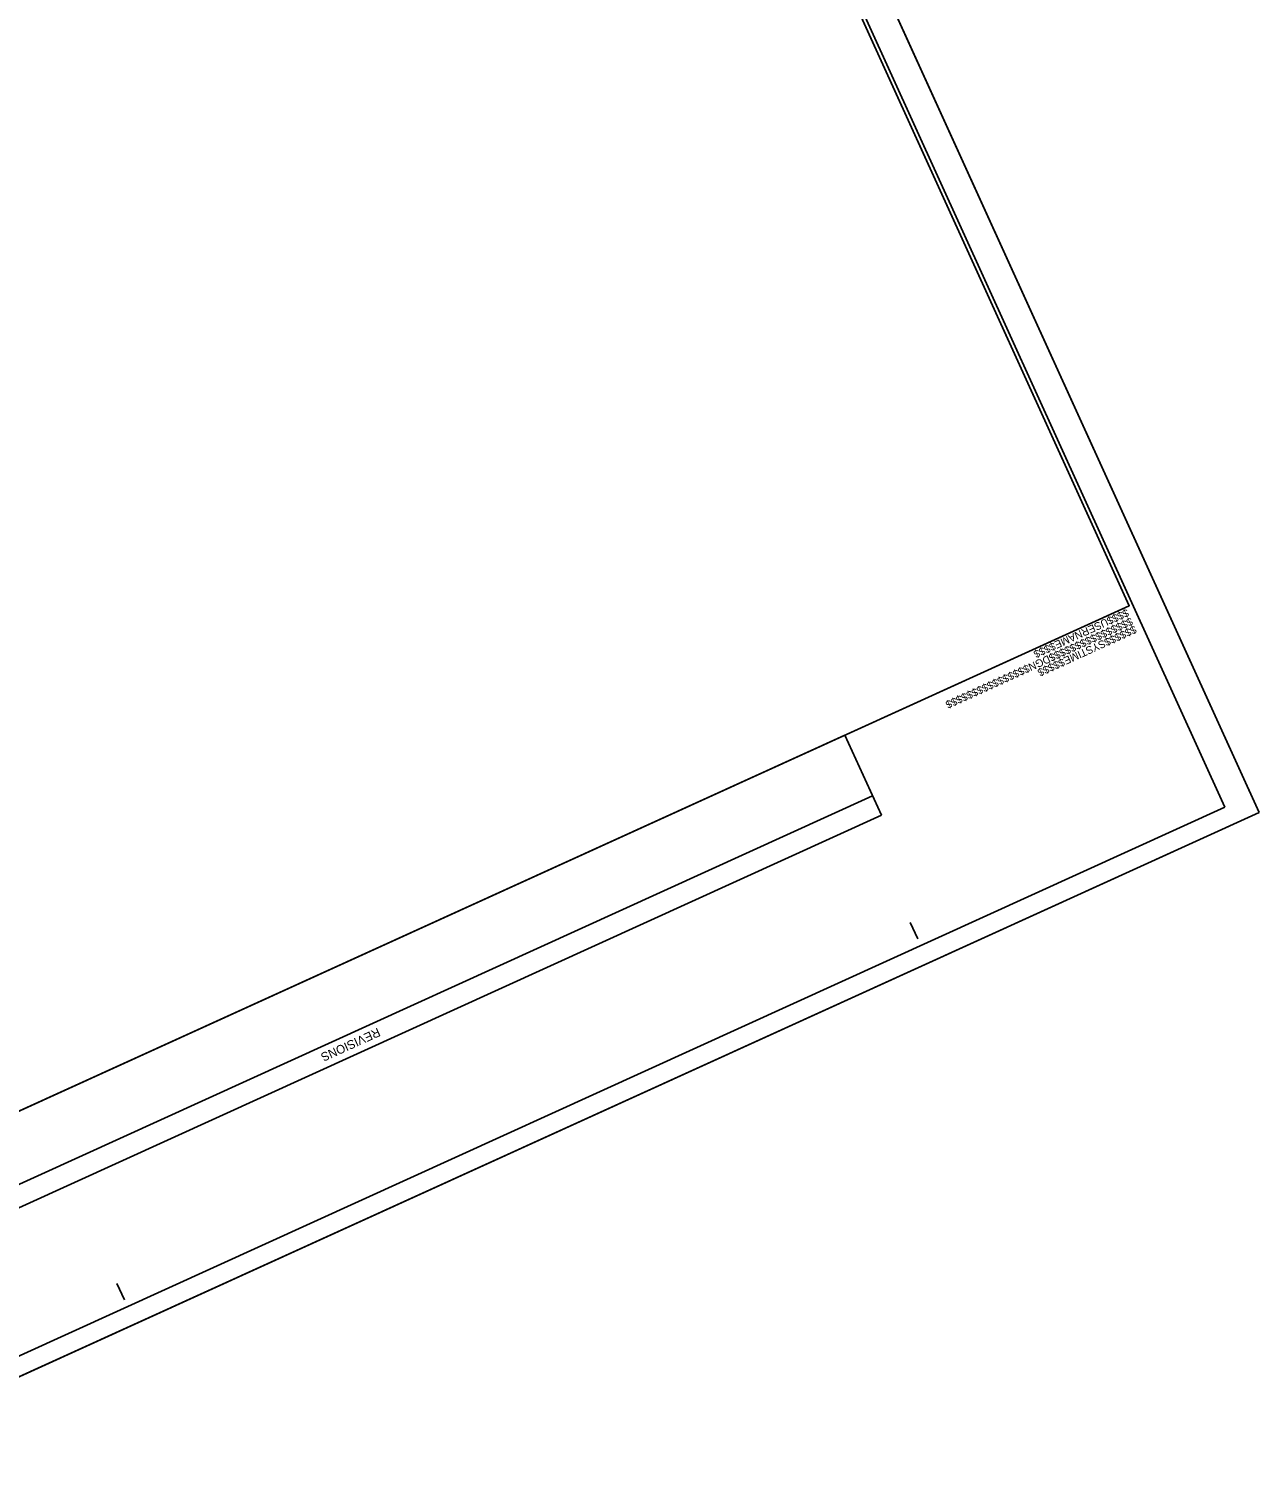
# Model space of a CAD drawing. Extents: x 2097293 to 2098987, y 683915 to 685901.
# Drawn here: x 2098140 to 2098987, y 683915 to 684908 of the extents above; entities that cross this region are included whole.
import ezdxf

# ---------------------------------------------------------------- set-up
doc = ezdxf.new("R2010")
doc.units = 0
for name, color, linetype in [('Sheet Block Revision CELL', 7, 'Continuous'), ('Sheet Cutting Line CELL', 7, 'Continuous'), ('Sheet Layout Plan Border', 7, 'Continuous'), ('Sheet Plan CELL', 7, 'Continuous'), ('Sheet Plot Border Inside CELL', 7, 'Continuous'), ('Sheet Plot Border Outside CELL', 7, 'Continuous')]:
    doc.layers.add(name, color=color, linetype=linetype)

msp = doc.modelspace()

# ---------------------------------------------------------------- linework, layer by layer
at = {"layer": 'Sheet Block Revision CELL'}
msp.add_line((2098720.62, 684379.88), (2098000.99, 684052.41), dxfattribs=at)
msp.add_lwpolyline([(2098726.67, 684366.65), (2098007.02, 684039.18), (2097981.92, 684094.27), (2098701.57, 684421.74)], close=True, dxfattribs=at)
at = {"layer": 'Sheet Cutting Line CELL'}
for p, q in [((2098986.71, 684368.56), (2098289.45, 685900.88)), ((2097990.05, 683915.04), (2098986.71, 684368.56))]:
    msp.add_line(p, q, dxfattribs=at)
at = {"layer": 'Sheet Layout Plan Border'}
for points in [[(2098897.26, 684510.8), (2097941.56, 684075.89), (2097486.05, 685076.91), (2097476.37, 685098.19), (2097403.15, 685259.11), (2097618.23, 685357), (2097567.61, 685468.23), (2098309.25, 685803.01)], [(2098897.26, 684510.8), (2097941.56, 684075.89), (2097486.05, 685076.91), (2097476.38, 685098.16), (2097403.15, 685259.11), (2097618.23, 685357), (2097567.61, 685468.23), (2098309.25, 685803.01)]]:
    msp.add_lwpolyline(points, close=True, dxfattribs=at)
at = {"layer": 'Sheet Plan CELL'}
for p, q in [((2098897.27, 684510.77), (2098897.27, 684510.77)), ((2098751.7, 684281.41), (2098746.54, 684292.8)), ((2098205.61, 684032.89), (2098200.4, 684044.27))]:
    msp.add_line(p, q, dxfattribs=at)
for points in [[(2097320.28, 685441.22), (2097941.56, 684075.89), (2098897.27, 684510.77), (2098276, 685876.08)], [(2098897.27, 684510.77), (2097941.59, 684075.88), (2097403.14, 685259.11), (2097539.72, 685321.27), (2097456.88, 685503.35), (2098276, 685876.08)]]:
    msp.add_lwpolyline(points, close=True, dxfattribs=at)
at = {"layer": 'Sheet Plot Border Inside CELL'}
msp.add_lwpolyline([(2098963.13, 684372.11), (2098273.1, 685888.48), (2097312.85, 685451.54), (2098002.87, 683935.16)], close=True, dxfattribs=at)
at = {"layer": 'Sheet Plot Border Outside CELL'}
msp.add_lwpolyline([(2098986.71, 684368.56), (2098289.45, 685900.88), (2097292.78, 685447.36), (2097990.05, 683915.04)], close=True, dxfattribs=at)

# ---------------------------------------------------------------- texts
at = {"layer": 'Sheet Block Revision CELL'}
msp.add_text('REVISIONS', height=6, rotation=204.46742, dxfattribs=at).set_placement((2098379.92, 684220.4))
at = {"layer": 'Sheet Plan CELL'}
for s, p in [('$$$$$$$$$$$$$$$$DGN$$$$$$$$$$$$$$$$', (2098898.28, 684502.84)), ('$$$$USERNAME$$$$', (2098895.56, 684508.8)), ('$$$$$$SYSTIME$$$$$', (2098900.82, 684497.32))]:
    msp.add_text(s, height=5.25, rotation=204.46742, dxfattribs=at).set_placement(p)

doc.saveas('drawing.dxf')
